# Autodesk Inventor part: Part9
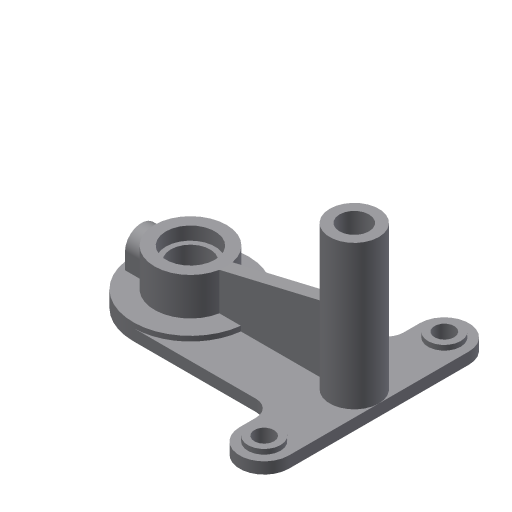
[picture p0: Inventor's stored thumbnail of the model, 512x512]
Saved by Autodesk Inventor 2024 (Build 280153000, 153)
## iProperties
Shininess: 77.0
Length Units: 11269
Angle Units: 11279
Time Units: 11290
Mass Units: 11283
Length Display Precision: 3
Angle Display Precision: 2
Created: 2001-12
Part Number: Part9
Document SubType Name: Modeling
Density: 1 g/cm^3
Material: Generic
Appearance: Default
Density: 0.0
Volumn: 0.0
Area: 0.0
PropertySet Name: Model Information
Control State: 0
Master: False
Checked Out: False
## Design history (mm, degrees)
sketch "Sketch1"
  geometry: L1 (46.121, -53.4)-(46.121, 56.6); L2 (16.121, 56.6)-(16.121, 36.6); L3 (16.121, 36.6)-(-68.879, 36.6); L4 (-68.879, -33.4)-(16.121, -33.4); L5 (16.121, -33.4)-(16.121, -53.4); A1 r 15 centre (31.121, 56.6) between (46.121, 56.6) and (16.121, 56.6); A2 r 35 centre (-68.879, 1.6) between (-68.879, 36.6) and (-68.879, -33.4); A3 r 15 centre (31.121, -53.4) between (16.121, -53.4) and (46.121, -53.4)
  constraints: 10 end point, 6 point on circle, 5 tangent, 3 centre point, 3 parallel, 2 equal length, 1 equal radius, 1 perpendicular, 1 vertical
  dimensions: "d0" = 15 radius of A1; "d1" = 110 distance of L1.start L1.end; "d2" = 100 horizontal distance of A3.centre A2.centre; "d3" = 35 radius of A2
extrude "Extrusion1" new body sketch "Sketch1" distance "d4" = 7; taper "d5" = 0 deg
sketch "Sketch2"
  geometry: C1 r 10 at (31.121, 56.6); C2 r 10 at (31.121, -53.4); C3 r 35 at (-68.879, 1.6); A1 r 35 centre (-68.879, 1.6) between (-68.879, 36.6) and (-68.879, -33.4) reference; A2 r 15 centre (31.121, 56.6) between (46.121, 56.6) and (16.121, 56.6) reference; A3 r 15 centre (31.121, -53.4) between (16.121, -53.4) and (46.121, -53.4) reference
  constraints: 3 centre point, 3 concentric, 2 equal radius
  dimensions: "d45" = 20 diameter of C1
extrude "Extrusion2" join sketch "Sketch2" distance "d6" = 3; taper "d7" = 0 deg
sketch "Sketch3"
  geometry: C1 r 22 at (0, 0); 1 further point
  constraints: 1 centre point, 1 coincident
  dimensions: "d8" = 44 diameter of C1
extrude "Extrusion3" join sketch "Sketch3" distance "d9" = 23; taper "d10" = 0 deg
sketch "Sketch4"
  geometry: L1 (46.121, 56.6)-(46.121, -53.4) reference; L2 (-68.879, 36.6)-(16.121, 36.6) reference; C1 r 15 at (31.121, 1.6)
  constraints: 1 centre point
  dimensions: "d11" = 30 diameter of C1; "d12" = 15 distance from line of L1 C1.centre; "d13" = 35 distance from line of L2 C1.centre
extrude "Extrusion4" join sketch "Sketch4" distance "d14" = 88; taper "d15" = 0 deg
workplane "Work Plane1"
feature "Rib1" dims "d21" = 1, "d22" = 8
workplane "Work Plane2"
workplane "Work Plane3"
sketch "Sketch7"
  geometry: L1 (10, 0)-(10, 10); L2 (-10, 10)-(-10, 0); L3 (-10, 0)-(10, 0); L4 (55, -10)-(55, -3) reference; A1 r 10 centre (0, 10) between (10, 10) and (-10, 10); 2 further points
  constraints: 6 end point, 2 point on circle, 2 tangent, 1 centre point, 1 parallel, 1 perpendicular, 1 vertical
  dimensions: "d30" = 10 radius of A1; "d34" = 55 distance from line of L4 A1.centre; "d35" = 10 distance of L1.start L1.end
extrude "Extrusion6" join sketch "Sketch7" stored distance "d36" = 88; taper "d37" = 0 deg
sketch "Sketch8"
  geometry: C1 r 10 at (0, 0) reference
hole "Hole1" sketch "Sketch8" diameter "d38" = 12; stored, may be unused: countersink angle "d42" = 82 deg, drill point angle "d44" = 118 deg; dims "d39" = 6, "d40" = 4, "d41" = 2, "d43" = 8
mirror "Mirror1"
sketch "Sketch9"
  geometry: C1 r 10 at (0, 0)
  constraints: 1 centre point
hole "Hole2" sketch "Sketch9" at (0, 0) diameter "d52" = 18; stored, may be unused: drill point angle "d47" = 118 deg, countersink angle "d48" = 82 deg; dims "d46" = 6, "d49" = 2, "d50" = 4, "d51" = 8
sketch "Sketch10"
  geometry: C1 r 10 at (0, 0)
  constraints: 1 centre point
hole "Hole3" sketch "Sketch10" at (0, 0) diameter "d59" = 24; stored, may be unused: drill point angle "d54" = 118 deg, countersink angle "d55" = 82 deg; dims "d53" = 6, "d56" = 8, "d57" = 30, "d58" = 8
sketch "Sketch11"
  geometry: C1 r 10 at (0, 0)
  constraints: 1 centre point
hole "Hole4" sketch "Sketch11" at (0, 0) diameter "d66" = 10; stored, may be unused: drill point angle "d61" = 0 deg, countersink angle "d62" = 82 deg; dims "d60" = 6, "d63" = 2, "d64" = 4, "d65" = 8
fillet "Fillet1" dims "d67" = 10
body "Solid1"
sketch "Sketch5"
  geometry: L1 (22, 33.1)-(85, 48); L2 (0, 7)-(35, 7) reference; L3 (85, 0)-(85, 7) reference; L4 (115, 0)-(115, 7) reference; L5 (115, 0)-(85, 0) reference
  constraints: 2 end point
  dimensions: "d17" = 26.1 distance from line of L2 L1.start; "d18" = 63 distance from line of L3 L1.start; "d19" = 30 distance from line of L4 L1.end; "d20" = 48 distance from line of L5 L1.end
other parameters: "d16" = -35, "d29" = -8
